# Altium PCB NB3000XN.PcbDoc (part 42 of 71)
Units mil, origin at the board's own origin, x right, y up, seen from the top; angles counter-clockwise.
Board outline 9527.56 x 6929.77 mil, 6 copper layers (Top Layer, GND+SHIELD, MidLayer1, MidLayer2, P2 - 3V3+5V0, Bottom Layer), stack 62.375 mil thick; 832 components, 1027 nets, 4655 pads, 4981 vias.
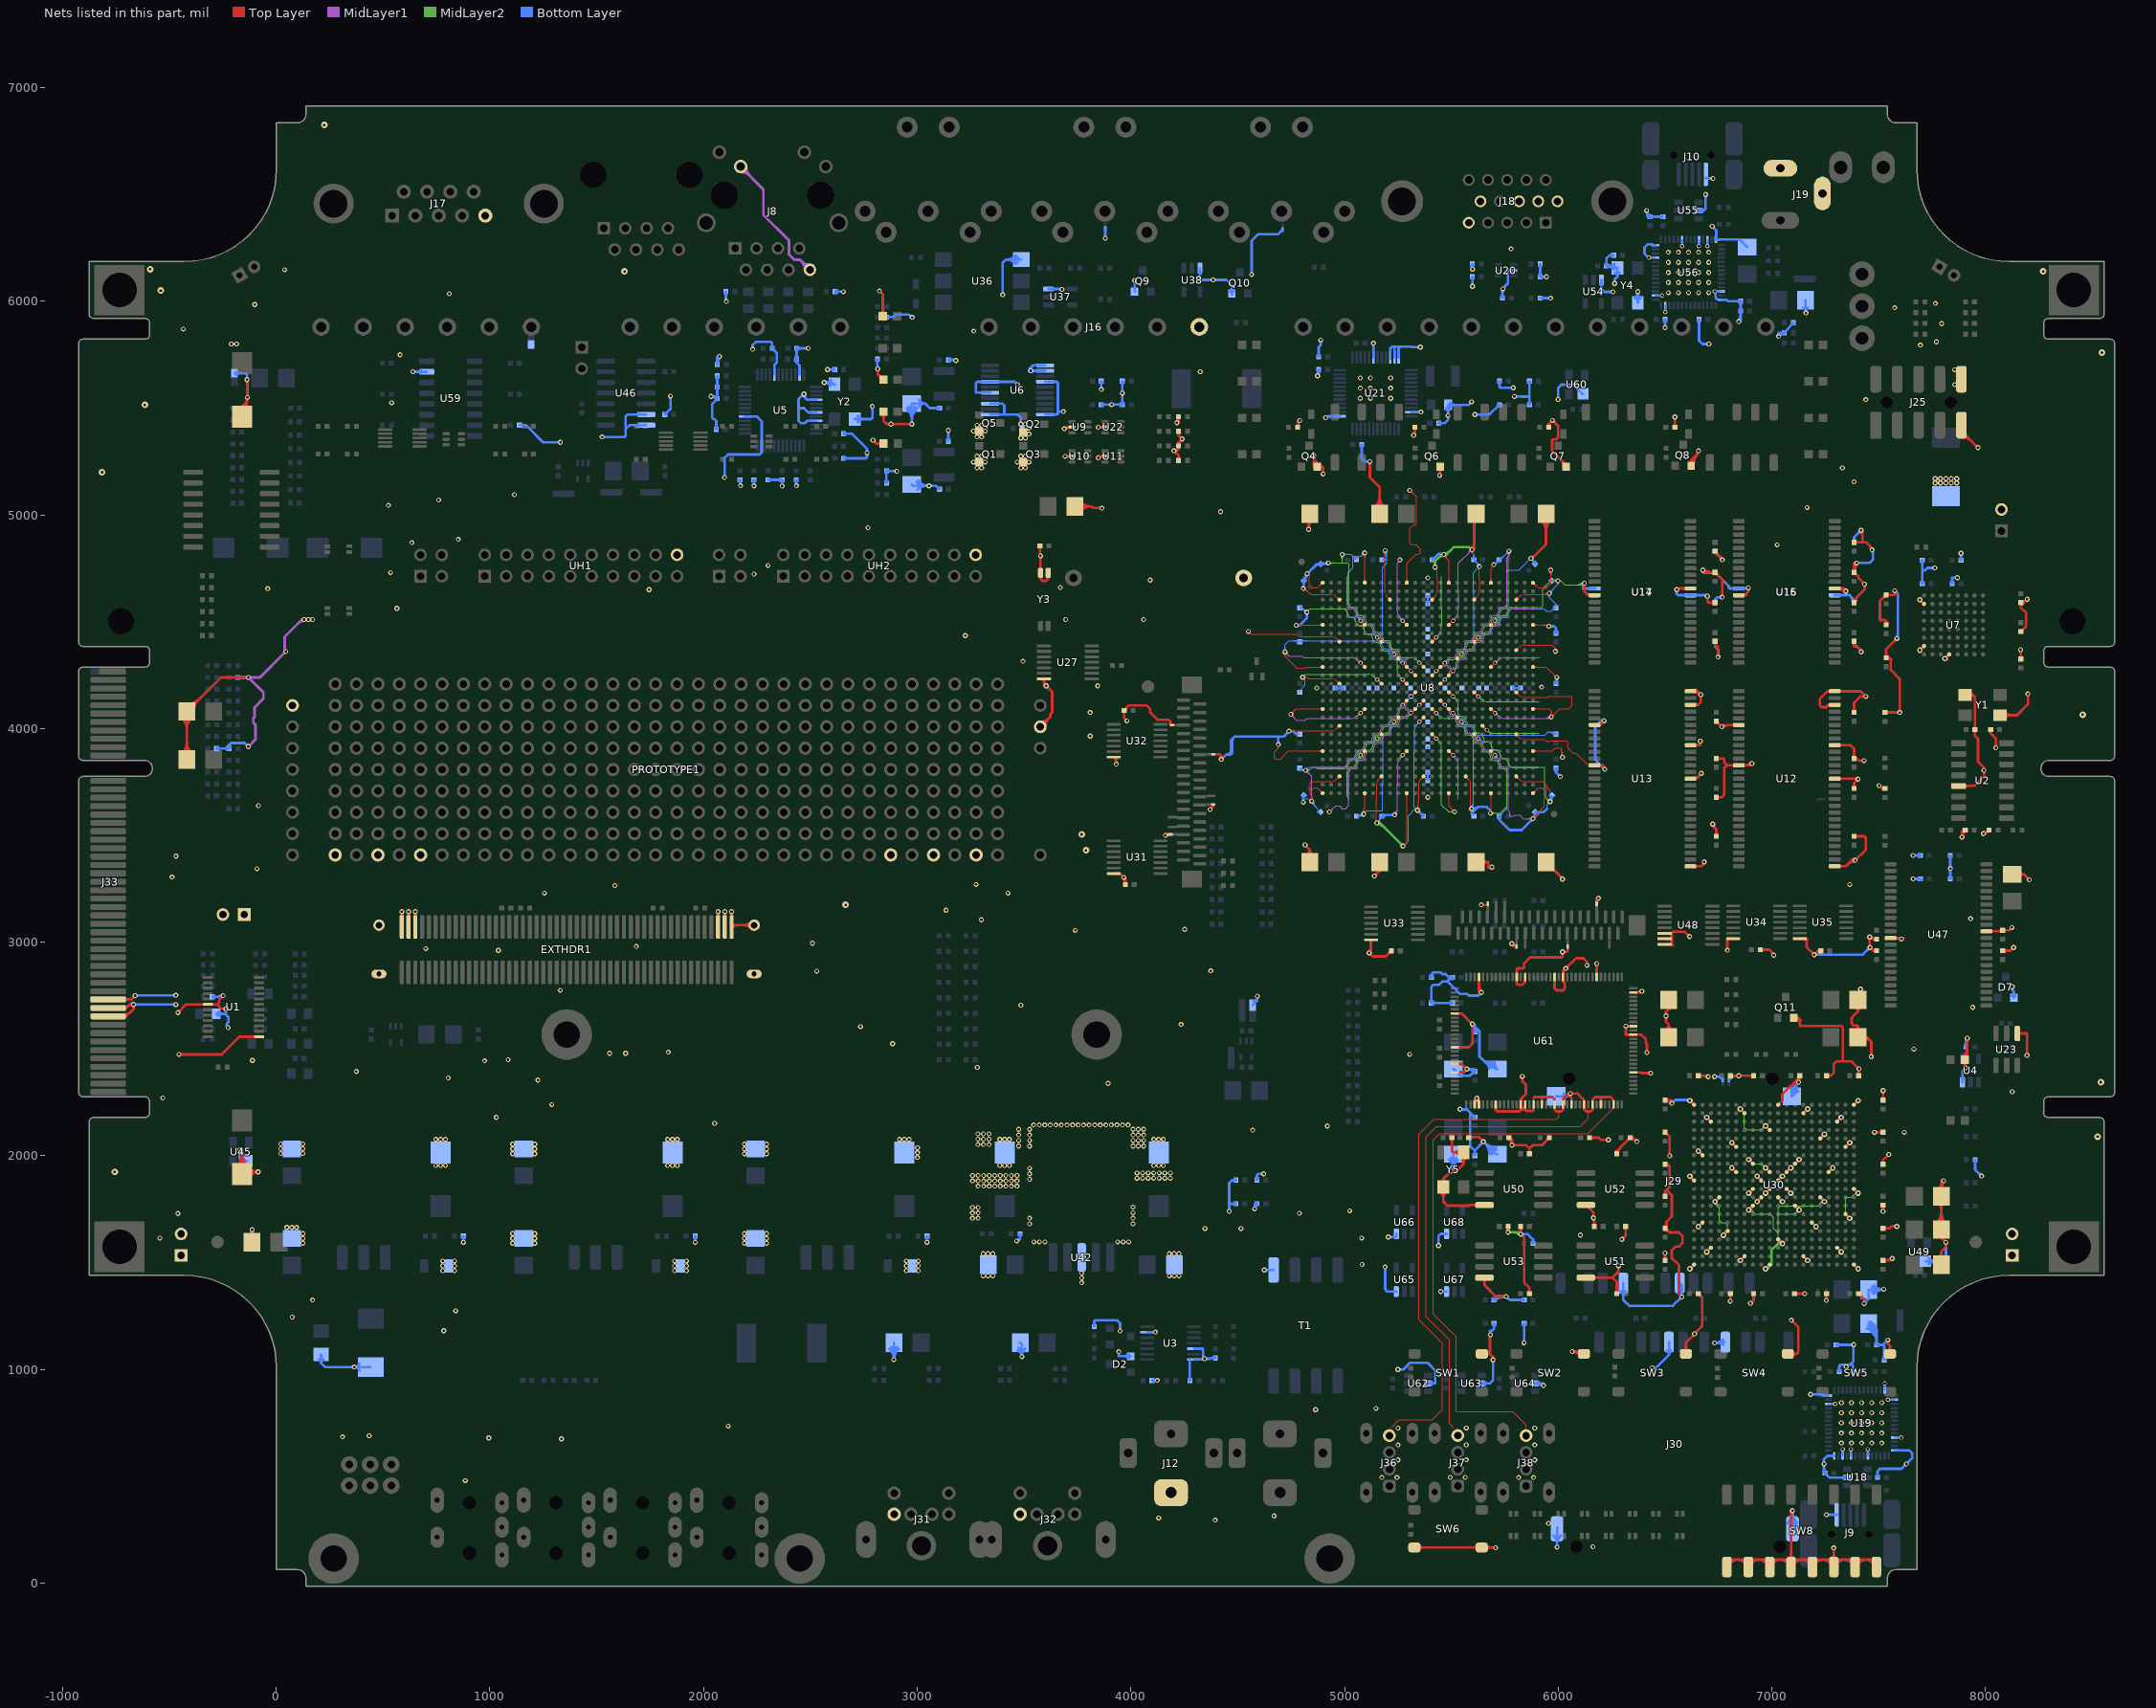
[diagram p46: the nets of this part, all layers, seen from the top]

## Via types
v1: diameter 23, hole 11.81, Top Layer to Bottom Layer, 3672 vias
v2: diameter 26, hole 11.81, Top Layer to Bottom Layer, 461 vias
v3: diameter 19, hole 11.81, Top Layer to Bottom Layer, tented both sides, 396 vias
v4: diameter 23.62, hole 11.81, Top Layer to Bottom Layer, 288 vias
v5: diameter 20, hole 11.81, Top Layer to Bottom Layer, 91 vias
v6: diameter 23, hole 11.81, Top Layer to Bottom Layer, tented both sides, 50 vias
v7: diameter 31, hole 11.81, Top Layer to Bottom Layer, 15 vias
v8: diameter 27.56, hole 11.81, Top Layer to Bottom Layer, tented both sides, 4 vias
v9: diameter 29, hole 11.81, Top Layer to Bottom Layer, 3 vias
v10: diameter 21, hole 11.81, Top Layer to Bottom Layer, 1 vias

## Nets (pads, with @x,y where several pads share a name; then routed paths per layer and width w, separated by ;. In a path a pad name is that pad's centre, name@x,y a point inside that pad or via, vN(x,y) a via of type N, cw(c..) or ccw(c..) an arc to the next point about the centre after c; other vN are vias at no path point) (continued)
GND: (continued)
  Top Layer w12: J33.A40@-785.98,2652.86 -701.48,2652.86 ; J33.A39@-785.98,2692.23 -701.48,2692.23 ; J33.A38@-785.98,2731.6 -678.25,2731.6 v1(-659.81,2750.04) ; J33.A39@-718.03,2688.12 ccw(c-713.87,2706.15) -700.79,2693.07 ; J33.A40@-717.08,2648.64 ccw(c-717.08,2676.13) -697.64,2656.69 ; J33.A40@-717.08,2660.64 ccw(c-717.08,2717.11) -677.16,2677.18 ; J33.A39@-715.33,2699.81 ccw(c-708.13,2731.03) -685.48,2708.37 ; J33.A38@-711.58,2726.1 cw(c-698.3,2712.82) -698.3,2731.6 cw(c-698.3,2750.38) J33.A38@-711.58,2737.1 ; J33.A40@-710.87,2648.18 cw(c-701.48,2641.09) -701.48,2652.86 ; J33.A40@-710.87,2657.54 ccw(c-701.48,2664.63) -701.48,2652.86 ; J33.A39@-710.87,2687.55 cw(c-701.48,2680.46) -701.48,2692.23 ; J33.A39@-710.87,2696.91 ccw(c-701.48,2704) -701.48,2692.23 ; -694.14,2699.71 cw(c-679.79,2685.36) v1@-670.63,2703.47 ; -686.64,2707.21 cw(c-668.14,2688.72) v1@-668.14,2714.87 ; -682.43,2711.42 cw(c-671.92,2700.91) v1@-665.21,2714.17 ; v1@-672.03,2712.26 cw(c-681.42,2721.65) -681.42,2708.37 cw(c-681.42,2695.1) -672.03,2704.49 cw(c-681.42,2695.1) -668.14,2695.1 cw(c-654.86,2695.1) v1@-664.25,2704.49 ; v1@-665.31,2750.04 cw(c-678.59,2750.04) -669.2,2740.65 cw(c-659.81,2731.26) v1@-659.81,2744.54 ; v4(-460,2670) -420.98,2709.02 U1.6@-320,2709.02 -276.78,2709.02 ; v4@-460,2675.81 ccw(c-460,2689.84) -450.08,2679.92 ccw(c-440.16,2670) v4@-454.19,2670 ; v4(-455,2475) -255,2475 -172.17,2557.83 U1.13@-79.84,2557.83 ; v4@-450.89,2470.89 cw(c-440.97,2460.97) -440.97,2475 cw(c-440.97,2489.03) v4@-450.89,2479.11 ; C191.2@-441.59,3882.53 ccw(c-498.56,3939.5) -417.99,3939.5 ; C3.2@-441.59,4052.47 cw(c-498.56,3995.5) -417.99,3995.5 cw(c-337.43,3995.5) C3.2@-394.4,4052.47 ; C191.2@-433.1,3874.05 ccw(c-469.58,3910.53) -417.99,3910.53 ccw(c-366.4,3910.53) C191.2@-402.88,3874.05 ; C3.2@-433.1,4060.95 cw(c-469.58,4024.47) -417.99,4024.47 cw(c-366.4,4024.47) C3.2@-402.88,4060.95 ; C191.2@-417.99,3855 -417.99,4041.71 -418.14,4041.71 -418.14,4080 -418.14,4083.07 -417.99,4083.22 C3.2@-417.99,4080 -258.62,4239.37 v1(-130.48,4239.37) ; -417.99,3939.5 ccw(c-337.43,3939.5) C191.2@-394.4,3882.53 ; C3.2@-417.99,4105.31 ccw(c-417.99,4166.4) -374.79,4123.2 ; C3.2@-417.99,4117.31 ccw(c-417.99,4207.37) -354.3,4143.69 ; C3.2@-396.62,4083.94 cw(c-354.53,4083.94) C3.2@-384.29,4113.7 ; C3.2@-384.62,4083.94 cw(c-313.56,4083.94) -363.81,4134.18 ; v1@-253.98,2750.04 cw(c-267.25,2750.04) -257.86,2740.65 cw(c-248.48,2731.26) v1@-248.48,2744.54 ; v1(-248.48,2750.04) -265.4,2733.12 -265.4,2720.4 -276.78,2709.02 ; v1@-238.36,2684.49 ccw(c-247.75,2675.1) -247.75,2688.37 ccw(c-247.75,2701.65) v1@-238.36,2692.26 ; v1(-234.48,2688.37) -256.14,2688.37 -276.78,2709.02 ; C2.2@-188.68,1947.4 ccw(c-256.93,2016.62) -159.72,2016.62 ; C2.2@-180.26,1938.86 ccw(c-228.64,1987.93) -159.72,1987.93 ccw(c-90.8,1987.93) C2.2@-139.19,1938.86 ; v1@-175.03,2024.15 cw(c-211.99,1987.2) -159.72,1987.2 ; C1.2@-171.72,5502.49 ccw(c-186.17,5550.04) v1@-136.48,5550.04 ; v1(-171.14,2028.04) -159.72,2016.62 ; C1.2@-168.23,5491.01 ccw(c-181.25,5533.85) -136.48,5533.85 ; v1@-166.55,2032.64 cw(c-183.02,2016.17) -159.72,2016.17 ; C1.2@-164.74,5479.53 ccw(c-176.33,5517.66) -136.48,5517.66 ; C1.2@-159.72,5459.09 -136.48,5459.09 v1@-136.48,5550.04 ; v1@-140.36,5629.49 cw(c-149.75,5620.1) -136.48,5620.1 cw(c-123.2,5620.1) v1@-132.59,5629.49 ; C2.2@-137.61,1937.17 ccw(c-111.07,1960.15) -111.07,1925.04 ; C1.2@-136.48,5506.48 ccw(c-116.28,5506.48) C1.2@-130.56,5492.2 ; -136.48,5532.74 cw(c-117.51,5532.74) v1@-130.92,5546.15 ; -136.48,5567.34 ccw(c-117.51,5567.34) v1@-130.92,5553.93 ; v1(-136.48,5633.37) v1@-136.48,5550.04 ; v1@-134.36,4235.49 ccw(c-143.75,4226.1) -143.75,4239.37 ccw(c-143.75,4252.65) v1@-134.36,4243.26 ; C2.2@-133.1,1905.94 cw(c-103.44,1892.47) -103.44,1925.04 ; C2.2@-130.77,1947.4 cw(c-62.52,2016.62) -159.72,2016.62 ; C2.2@-128.54,1945.02 ccw(c-84.81,1982.87) v1(-84.81,1925.04) ; C4.2@-128.45,1628.51 ccw(c-141.8,1654.04) v1@-112.99,1654.04 ; C2.2@-122.17,1900.98 cw(c-84.81,1884.01) v1(-84.81,1925.04) ; v1@-116.7,1650.15 cw(c-125.65,1641.2) -112.99,1641.2 ; C4.2@-112.99,1595 v1@-112.99,1654.04 ; -112.99,1640.32 cw(c-99.09,1640.32) v1@-108.92,1650.15 ; v1(-112.81,1654.04) v1@-112.99,1654.04 ; C4.2@-97.53,1628.51 cw(c-84.18,1654.04) v1@-112.99,1654.04 ; v1@-88.7,1921.15 ccw(c-98.09,1911.76) -98.09,1925.04 ccw(c-98.09,1938.32) v1@-88.7,1928.93 ; v1@-84.81,1924.76 v1(-84.81,1925.04) ; v1@583.97,3139.15 cw(c574.2,3129.38) 588.01,3129.38 ; v1(587.86,3143.04) 588.01,3142.88 EXTHDR1.99@588.01,3071.85 ; 588.01,3130.14 cw(c600.76,3130.14) v1@591.75,3139.15 ; v1@615.46,3139.15 cw(c605.7,3129.38) 619.51,3129.38 ; EXTHDR1.97@619.51,3071.85 v1@619.51,3142.88 ; 619.51,3130.14 cw(c632.25,3130.14) v1@623.24,3139.15 ; v1@646.96,3139.15 cw(c637.19,3129.38) 651.01,3129.38 ; EXTHDR1.95@651.01,3071.85 v1@651.01,3142.88 ; 651.01,3130.14 cw(c663.75,3130.14) v1@654.74,3139.15 ; v1@2064.28,3139.15 cw(c2054.52,3129.38) 2068.33,3129.38 ; EXTHDR1.5@2068.33,3071.85 v1@2068.33,3142.88 ; 2068.33,3130.14 cw(c2081.07,3130.14) v1@2072.06,3139.15 ; v1@2095.78,3139.15 cw(c2086.01,3129.38) 2099.83,3129.38 ; EXTHDR1.3@2099.83,3071.85 v1@2099.83,3142.88 ; 2099.83,3130.14 cw(c2112.57,3130.14) v1@2103.56,3139.15 ; v1@2127.28,3139.15 cw(c2117.51,3129.38) 2131.32,3129.38 ; EXTHDR1.1@2131.32,3071.85 v1@2131.32,3142.88 ; EXTHDR1.1@2131.32,3079.72 EXTHDR1.MH1@2236.94,3079.72 ; 2131.32,3130.14 cw(c2144.07,3130.14) v1@2135.06,3139.15 ; EXTHDR1.1@2134.15,3069.02 cw(c2159.99,3043.18) 2159.99,3079.72 ; EXTHDR1.MH1@2222.39,3065.17 ccw(c2187.27,3030.05) 2187.27,3079.72 ccw(c2187.27,3129.39) EXTHDR1.MH1@2222.39,3094.27 ; v1@2793.19,5344.54 cw(c2793.19,5331.26) 2802.58,5340.65 cw(c2811.97,5350.04) v1@2798.69,5350.04 ; v1(2793.19,5350.04) 2809.52,5333.71 ; v1@2811.3,5679.49 cw(c2801.91,5670.1) 2815.19,5670.1 cw(c2828.47,5670.1) v1@2819.08,5679.49 ; v1(2815.19,5683.37) 2815.19,5660.15 LED5.2@2842.08,5633.26 ; v1(2823.52,6048.37) 2839.27,6032.63 LED4.2@2839.27,5930 ; LED5.2@2828.4,5633.26 ccw(c2795.36,5633.26) 2818.72,5656.62 ccw(c2842.08,5679.99) LED5.2@2842.08,5646.95 ; LED4.2@2829.6,5939.68 ccw(c2806.23,5963.04) 2839.27,5963.04 ccw(c2872.31,5963.04) LED4.2@2848.95,5939.68 ; LED7.2@2832.37,5324.12 ccw(c2809.52,5301.69) 2809.52,5333.71 ; LED7.2@2832.37,5343.3 cw(c2809.52,5365.74) 2809.52,5333.71 ; LED6.2@2832.41,5473.79 cw(c2809.04,5450.43) 2842.08,5450.43 cw(c2875.12,5450.43) LED6.2@2851.76,5473.79 ; LED6.2@2842.08,5483.47 2842.08,5440.99 2858.07,5425 v1(2975,5425) ; LED7.2@2842.14,5333.71 2809.52,5333.71 ; v1@2971.11,5421.11 ccw(c2961.72,5411.72) 2961.72,5425 ccw(c2961.72,5438.28) v1@2971.11,5428.89 ; C116.2@3570.22,4850.89 cw(c3560.3,4840.97) 3574.33,4840.97 cw(c3588.36,4840.97) C116.2@3578.44,4850.89 ; Y3.3@3573.17,4713.1 cw(c3563.25,4703.17) 3577.28,4703.17 cw(c3591.31,4703.18) Y3.3@3581.39,4713.1 ; Y3.3@3573.17,4744.94 ccw(c3563.25,4754.86) 3577.28,4754.86 ccw(c3591.31,4754.85) Y3.3@3581.39,4744.94 ; v1@3573.4,4804.73 cw(c3564.01,4795.34) 3577.28,4795.34 cw(c3590.56,4795.34) v1@3581.17,4804.73 ; 3574.33,4829.02 ccw(c3597.69,4829.02) v1@3581.17,4812.5 ; C116.2@3574.33,4855 3574.33,4811.57 v1(3577.28,4808.61) Y3.3@3577.28,4729.02 3577.28,4700.04 3585.62,4691.71 3604.38,4691.71 3612.72,4700.04 Y3.2@3612.72,4729.02 ; TP8.1@3576.12,4008.23 3623.09,4055.2 3623.09,4065.94 3631.86,4074.71 3631.86,4172.04 v1(3603.86,4200.04) ; TP8.1@3576.12,4032.23 ccw(c3576.12,4090.18) 3617.09,4049.21 ccw(c3658.06,4008.23) TP8.1@3600.12,4008.23 ; 3592.8,4209.18 ccw(c3610.73,4209.18) v1@3599.95,4194.85 ; v1@3598.52,4200.04 v1(3603.86,4200.04) ; v1@3603.86,4194.54 cw(c3603.86,4181.26) 3613.25,4190.65 cw(c3622.64,4200.04) v1@3609.36,4200.04 ; v1@3607.16,4204.44 cw(c3628.82,4233.23) U27.7@3592.8,4233.23 3592.8,4211.1 v1(3603.86,4200.04) ; Y3.2@3608.61,4713.1 cw(c3598.69,4703.17) 3612.72,4703.17 cw(c3626.74,4703.18) Y3.2@3616.83,4713.1 ; v1@3689.9,5397.84 cw(c3716.14,5371.6) U9.2@3716.14,5408.72 ; v1@3692.31,5274.49 v1(3692.19,5274.37) U10.2@3725,5274.41 ; v1@3692.31,5400.26 3702.64,5410.59 U9.2@3725,5410.59 ; v1@3695.89,5403.84 cw(c3709.89,5389.84) U9.2@3715.6,5408.8 ; v1@3696.08,5270.49 cw(c3705.55,5261.01) 3705.55,5274.41 ; v1@3696.08,5278.26 ccw(c3705.39,5287.57) 3705.39,5274.41 ; C115.2@3737.99,5040 3814.23,5040 ; C115.2@3753.69,5025.5 cw(c3786.81,4994.92) 3786.81,5040 cw(c3786.81,5085.08) C115.2@3753.69,5054.5 ; C115.2@3762.51,5017.36 cw(c3814.23,4969.6) 3814.23,5040 ; C115.2@3762.51,5062.64 ccw(c3814.23,5110.4) 3814.23,5040 ; 3846.42,5033.37 cw(c3846.42,5013.27) v1@3860.64,5027.49 ; v1(3847.19,5267.04) v1@3847.19,5274.37 ; v1(3847.19,5410.71) 3847.31,5410.59 U22.2@3880,5410.59 ; v1@3847.22,5274.41 U11.2@3880,5274.41 ; v1@3851.08,5263.15 cw(c3878.26,5235.97) U11.2@3878.26,5274.41 ; v1@3851.08,5406.82 cw(c3860.18,5397.71) 3860.18,5410.59 ; v1@3851.08,5414.6 ccw(c3860.75,5424.27) 3860.75,5410.59 ; v1(3864.52,5031.37) 3856.19,5031.37 3854.19,5033.37 3820.86,5033.37 3814.23,5040 ; U31.7@3920,3321.46 3949.11,3321.46 v1(3966.86,3303.71) 3974.33,3296.23 C124.1@3974.33,3270 ; U32.7@3926.46,3865 3931.86,3859.6 v1(3931.86,3833.37) ; U32.7@3926.46,3866.46 U32.7@3920,3866.46 ; v1@3927.97,3837.26 ccw(c3918.58,3846.65) 3931.86,3846.65 ccw(c3945.14,3846.65) v1@3935.75,3837.26 ; U32.7@3928.54,3862.92 ccw(c3920,3854.39) U32.7@3920,3866.46 ; v1@3931.86,3837.83 ccw(c3891.37,3837.83) U32.7@3920,3866.46 ; 3931.86,3852.76 ccw(c3918.02,3852.76) U32.7@3920,3866.46 ; v1@3961.36,3303.71 ccw(c3948.08,3303.71) 3957.47,3313.1 ccw(c3966.86,3322.49) v1@3966.86,3309.21 ; v1@3962.97,3299.82 cw(c3935.54,3272.39) C124.1@3974.33,3272.39 ; 3969.19,4070.63 cw(c3983.7,4070.63) 3973.44,4080.89 ccw(c3983.36,4070.97) 3969.33,4070.97 ccw(c3955.3,4070.97) 3965.22,4080.89 cw(c3955.64,4071.31) 3969.19,4071.31 ; 3969.33,4056.71 C121.1@3969.33,4085 ; C124.1@3970.22,3274.11 ccw(c3960.3,3284.03) 3974.33,3284.03 ccw(c3988.36,3284.03) C124.1@3978.44,3274.11 ; C121.1@3975.14,4085 cw(c3995.24,4085) 3981.03,4099.21 ; v1(3981.86,4036.04) 3969.19,4048.71 3969.19,4085 3969.19,4087.37 3990.19,4108.37 4073.52,4108.37 4090.19,4091.71 4090.19,4075.04 4123.52,4041.71 4176.67,4041.71 4185,4033.37 NT28.2@4185,4020 ; v1(4161.86,3500.04) 4161.86,3508.33 4165.19,3505 NT31.2@4185,3505 ccw(c4185,3479.67) v1@4165.99,3496.41 ; 4185,4022.71 ccw(c4193.8,4022.71) NT28.2@4187.58,4016.49 ; v1@4201.86,5294.54 cw(c4201.86,5281.26) 4211.25,5290.65 cw(c4220.64,5300.04) v1@4207.36,5300.04 ; v1@4204.22,5305.01 ccw(c4211.64,5320.55) 4223.82,5308.37 ; v1@4212.18,5436.41 ccw(c4194.09,5460) R124.1@4223.82,5460 ; v1(4215.52,5432.04) 4216.86,5433.37 4222.78,5433.37 4223.82,5434.41 R124.1@4223.82,5460 ; R93.1@4217.17,5323.16 cw(c4234.81,5324.92) 4222.28,5337.46 ; R95.1@4220.06,5259.25 ccw(c4210.98,5268.33) 4223.82,5268.33 ccw(c4236.66,5268.33) R95.1@4227.58,5259.25 ; R93.1@4220.06,5319.08 cw(c4210.98,5310) 4223.82,5310 ; R93.1@4220.06,5327.59 ccw(c4210.98,5336.67) 4223.82,5336.67 ccw(c4236.66,5336.67) R93.1@4227.58,5327.59 ; R91.1@4220.06,5387.41 cw(c4210.98,5378.33) 4223.82,5378.33 cw(c4236.66,5378.33) R91.1@4227.58,5387.41 ; R124.1@4220.06,5455.75 cw(c4210.98,5446.67) 4223.82,5446.67 cw(c4236.66,5446.67) R124.1@4227.58,5455.75 ; R95.1@4223.82,5255 4223.82,5278.08 v1(4201.86,5300.04) 4215.49,5300.04 4223.82,5308.37 ; 4223.82,5310 cw(c4236.66,5310) R93.1@4227.58,5319.08 ; R91.1@4223.82,5391.67 4223.82,5371.71 4228.82,5366.71 ; 4228.86,5366.71 v1(4240.19,5355.37) ; R93.1@4229.11,5324.35 cw(c4267.39,5328.17) v1(4240.19,5355.37) ; 4230.74,5364.79 ccw(c4240.19,5374.24) v1@4240.19,5360.87 ; 4230.83,5364.7 cw(c4221.5,5355.37) 4234.69,5355.37 cw(c4221.41,5355.37) 4230.8,5345.99 cw(c4240.19,5336.6) v1@4240.19,5349.87 ; v1(4370.52,3621.37) 4385,3635.85 NT30.2@4385,3645 ; v1@4377.35,3628.2 ccw(c4366.65,3638.9) NT30.2@4380.5,3645 ; NT29.2@4385,3880 4414.86,3880 4418.86,3876 ; 4418.86,3876 ccw(c4438.69,3876) v1@4426.82,3860.11 ; 4425.76,3869.1 cw(c4414.72,3858.06) v1@4429.8,3854.03 ; R97.1@4777.42,5414.25 ccw(c4768.34,5423.33) 4781.18,5423.33 ccw(c4794.02,5423.33) R97.1@4784.94,5414.25 ; R97.1@4781.18,5408.75 cw(c4820.38,5408.75) v1@4793.9,5437.65 ; R97.1@4781.18,5410 4781.18,5432.71 v1(4790.19,5441.71) ; v1@4815.19,3450.21 cw(c4815.19,3436.93) 4824.58,3446.32 cw(c4833.97,3455.71) v1@4820.69,3455.71 ; v1(4815.19,3455.71) 4837.01,3433.89 ; C278.2@4821.62,3408.55 ccw(c4808.45,3433.89) 4837.01,3433.89 ; v1@4827.97,4936.26 ccw(c4818.58,4945.65) 4831.86,4945.65 ccw(c4845.14,4945.65) v1@4835.75,4936.26 ; C276.2@4830.3,4968.37 cw(c4828.61,4960.15) 4837.01,4960.15 ; v1(4831.86,4932.37) 4831.86,4955 4837.01,4960.15 ; C278.2@4837.01,3375 4837.01,3433.89 ; C276.2@4837.01,5005 4837.01,4960.15 ; C276.2@4843.71,4968.37 ccw(c4845.4,4960.15) 4837.01,4960.15 ; C278.2@4852.4,3408.55 cw(c4865.57,3433.89) 4837.01,3433.89 ; v1@4852.97,5273.82 cw(c4843.58,5264.43) 4856.86,5264.43 cw(c4870.14,5264.43) v1@4860.75,5273.82 ; Q4.3@4856.86,5225.79 v1(4856.86,5277.71) ccw(c4906.35,5277.71) Q4.3@4878.9,5236.52 ; 4856.86,5255.29 ccw(c4891.41,5255.29) Q4.3@4872.24,5226.54 ; Q4.3@4872.22,5225.02 cw(c4883.53,5211.12) 4896.21,5223.79 ; Q4.3@4872.28,5225.06 cw(c4882.73,5203.89) 4899.42,5220.58 ; Q4.3@4872.4,5225.79 4894.21,5225.79 ; Q4.3@4882.17,5219.32 cw(c4894.21,5211.35) 4894.21,5225.79 ; Q4.3@4882.17,5232.26 ccw(c4894.21,5240.23) 4894.21,5225.79 ; v1@4895.97,5195.6 ccw(c4886.58,5204.99) 4899.86,5204.99 ccw(c4913.14,5204.99) v1@4903.75,5195.6 ; v1(4899.86,5191.71) 4899.86,5220.14 4894.21,5225.79 ; v1@5111.3,2953.93 ccw(c5081.79,2983.44) 5123.52,2983.44 ; v1@5114.97,5246.15 cw(c5105.58,5236.76) 5118.86,5236.76 cw(c5132.14,5236.76) v1@5122.75,5246.15 ; v1@5115.19,2944.54 cw(c5115.19,2931.26) 5124.58,2940.65 cw(c5133.97,2950.04) v1@5120.69,2950.04 ; v1(5118.86,5250.04) 5118.86,5176.14 5164.33,5130.67 5164.33,5107.04 C260.2@5164.33,5005 ; U33.7@5123.52,3011.46 5123.52,2958.37 v1(5115.19,2950.04) 5131.86,2933.37 5192.71,2933.37 C122.1@5219.33,2960 ; v1(5140,3310) 5164.33,3334.33 C265.2@5164.33,3375 ; v1@5140,3315.5 ccw(c5140,3328.78) 5149.39,3319.39 ccw(c5158.78,3310) v1@5145.5,3310 ; C260.2@5140.73,5032.53 ccw(c5083.77,5089.5) 5164.33,5089.5 ; C260.2@5149.22,5024.05 ccw(c5112.74,5060.53) 5164.33,5060.53 ccw(c5215.92,5060.53) C260.2@5179.44,5024.05 ; 5164.33,5089.5 ccw(c5244.89,5089.5) C260.2@5187.93,5032.53 ; C122.1@5213.52,2960 cw(c5199.49,2960) 5209.41,2950.08 cw(c5219.33,2940.16) C122.1@5219.33,2954.19 ; v1@5319.64,5376.26 ccw(c5297.46,5398.44) R126.1@5328.82,5398.44 ; v1(5323.52,5372.37) 5323.52,5370.37 5323.82,5370.37 5324.67,5371.23 5328.82,5375.37 R126.1@5328.82,5410 ; R126.1@5325.06,5405.75 cw(c5315.98,5396.67) 5328.82,5396.67 cw(c5341.66,5396.67) R126.1@5332.58,5405.75 ; SW6.3@5327.13,166.81 5392.63,166.81 5392.52,166.71 5598.52,166.71 5598.52,166.81 ; SW6.3@5344.79,155.14 cw(c5372.96,126.98) 5372.96,166.81 cw(c5372.96,206.65) SW6.3@5344.79,178.48 ; Q6.3@5439.45,5216.19 cw(c5422.7,5198.04) 5447.4,5198.04 ; v1@5441.11,5188.89 ccw(c5425.92,5204.08) 5447.4,5204.08 ; v1(5445,5185) 5441.82,5185 5440.19,5183.37 5440.19,5191.04 5440.4,5191.04 5447.4,5198.04 ; Y5.2@5447.3,1834.3 cw(c5410.59,1797.59) 5462.5,1797.59 cw(c5514.41,1797.59) Y5.2@5477.7,1834.3 ; Q6.3@5447.4,5225.79 5447.4,5198.04 ; Y5.2@5453.02,1876.8 ccw(c5445.55,1892.02) 5462.5,1892.02 ; Q6.3@5455.35,5216.19 ccw(c5472.11,5198.04) 5447.4,5198.04 ; Y5.2@5471.98,1876.8 cw(c5479.46,1892.02) 5462.5,1892.02 ; v1@5493.02,1928.04 cw(c5479.75,1928.04) 5489.14,1918.65 cw(c5498.52,1909.26) v1@5498.52,1922.54 ; C157.1@5498.56,2080.89 cw(c5488.64,2070.97) 5502.67,2070.97 cw(c5516.7,2070.97) C157.1@5506.78,2080.89 ; v1@5502.41,1924.15 cw(c5511.8,1914.76) 5511.8,1928.04 cw(c5511.8,1941.32) v1@5502.41,1931.93 ; C157.1@5502.67,2085 5502.67,2022.33 5508.5,2016.5 ; U61.123@5516.83,2390.4 5556.55,2390.4 v1(5572.52,2406.37) 5549.13,2429.77 U61.121@5516.83,2429.77 ; U61.117@5516.83,2508.51 5548.52,2508.51 5548.52,2508.37 5581.86,2508.37 5598.52,2525.04 v1(5598.52,2616.71) 5549.24,2665.99 U61.109@5516.83,2665.99 ; Y5.4@5541.68,2001.94 ccw(c5508.5,1971.42) 5508.5,2016.5 ; Y5.4@5541.68,2031.06 cw(c5508.5,2061.58) 5508.5,2016.5 ; Y5.4@5542.6,1997 cw(c5508.99,1962.02) 5557.5,1962.02 ; Y5.4@5572.4,1997 ccw(c5606.01,1962.02) 5557.5,1962.02 ; v1@5572.52,2400.87 ccw(c5572.52,2387.6) 5563.14,2396.99 ccw(c5553.75,2406.37) 5567.02,2406.37 ccw(c5553.75,2406.37) 5563.14,2415.76 ccw(c5572.52,2425.15) v1@5572.52,2411.87 ; C169.1@5580.67,2085 5583.54,2087.87 5629.36,2087.87 v1(5650.52,2066.71) ; C169.1@5584.78,2080.89 cw(c5601.64,2064.03) 5601.64,2087.87 ; v1@5592.3,4840.93 ccw(c5557.16,4876.07) 5606.86,4876.07 ; v1@5593.02,2616.71 ccw(c5579.75,2616.71) 5589.14,2626.1 ccw(c5598.52,2635.49) v1@5598.52,2622.21 ; v1@5594.64,2612.82 cw(c5585.25,2603.43) 5598.52,2603.43 cw(c5611.8,2603.43) v1@5602.41,2612.82 ; v1(5596.19,4837.04) 5606.86,4847.71 C267.2@5606.86,5000.04 ; v1@5600.79,4832.44 ccw(c5586.13,4847.1) 5606.86,4847.1 ; U61.3@5609.37,2238.17 cw(c5642.58,2238.17) v4@5623.36,2265.26 ; U61.3@5609.37,2240 5609.37,2260.37 v4@5620,2260.37 ; 5609.37,2261.4 cw(c5626.1,2261.4) v4@5616.42,2275.05 ; 5611.72,2260.37 cw(c5611.72,2235.85) U61.4@5629.06,2253.19 ; C266.2@5615.67,3375 5671.48,3375 ; v4@5616.32,2265.5 cw(c5594.41,2238.66) U61.4@5629.06,2238.66 ; U50.4@5619.97,1764.5 ccw(c5606.69,1751.22) 5606.69,1770 ccw(c5606.69,1788.78) U50.4@5619.97,1775.5 ; v4(5620,2270) v4@5620,2260.37 ; SW6.4@5624.41,155.56 ccw(c5598.53,131.41) 5598.53,166.81 ; SW6.4@5624.41,178.07 cw(c5598.53,202.21) 5598.53,166.81 ; v4@5626.71,2260.37 ccw(c5626.71,2235.85) U61.3@5609.37,2253.19 ; U61.4@5629.06,2240 5629.06,2260.37 v4@5620,2260.37 ; 5629.06,2775.57 ccw(c5651.38,2775.57) v1@5635.59,2759.78 ; 5629.06,2804.54 ccw(c5680.35,2804.54) v1@5644.08,2768.26 ; U61.99@5629.06,2837.34 5629.06,2775.51 v1(5640.19,2764.37) ; SW1.3@5642.87,1073.58 5680.86,1073.58 ; v1@5645.02,2066.71 ccw(c5631.75,2066.71) 5641.14,2076.1 ccw(c5650.52,2085.49) v1@5650.52,2072.21 ; C266.2@5645.06,3359.21 cw(c5671.48,3345.01) 5671.48,3375 ; C266.2@5645.07,3390.79 ccw(c5671.48,3404.99) 5671.48,3375 ; U53.4@5649.5,1424.5 cw(c5636.22,1411.22) 5655,1411.22 cw(c5673.78,1411.22) U53.4@5660.5,1424.5 ; U53.4@5655,1430 5655,1395 5708.29,1341.71 v1(5756.86,1341.71) ; U50.4@5655,1770 5585.86,1770 5582.86,1767 5582.86,1766.71 5481.83,1766.71 5462.5,1786.04 Y5.2@5462.5,1853.5 Y5.2@5462.5,1855.99 ; SW6.4@5660.15,155.14 cw(c5688.31,126.98) 5688.31,166.81 cw(c5688.32,206.65) SW6.4@5660.15,178.48 ; SW1.3@5662.32,1064.02 cw(c5680.86,1050.84) 5680.86,1073.58 ; SW1.3@5662.32,1083.15 ccw(c5680.86,1096.33) 5680.86,1073.58 ; 5671.86,3375.04 5673.52,3373.37 5673.52,3351.71 ; 5673.52,3350.71 5677.52,3346.71 5690,3346.71 5695,3346.71 v4(5690,3351.71) ; 5680.86,1143.66 cw(c5701.57,1143.66) v1@5686.92,1158.3 ; v1(5683.03,1162.19) 5683.03,1165.53 5680.86,1167.71 5680.86,1073.58 ; 5690.92,166.81 cw(c5690.92,149.77) v1@5702.97,161.82 ; v1(5695,1045) 5695,1059.44 5680.86,1073.58 ; 5695.89,1058.55 cw(c5682.33,1045) v1@5701.5,1045 ; v1(5706.86,165.71) 5707.96,166.81 5706.86,166.81 SW6.4@5642.48,166.81 5598.52,166.81 ; U61.8@5707.8,2226.81 ccw(c5717.39,2221.61) 5709.67,2213.89 ; U61.8@5707.79,2240 5707.8,2217.37 5707.13,2216.71 5706.86,2216.71 5715.19,2208.37 5819.95,2208.37 5823.52,2211.95 ; v1@5752.97,1337.82 ccw(c5743.58,1328.43) 5743.58,1341.71 ccw(c5743.58,1354.99) v1@5752.97,1345.6 ; v1@5761.45,1646.26 ccw(c5751.25,1656.46) 5765.67,1656.46 ; C158.2@5761.56,1665.89 cw(c5751.64,1655.97) 5765.67,1655.97 cw(c5779.7,1655.97) C158.2@5769.78,1665.89 ; v1(5765.34,1642.37) 5765.67,1642.71 C158.2@5765.67,1670 ; 5765.67,1654.85 ccw(c5777.81,1654.85) v1@5769.22,1646.26 ; C187.2@5766.19,2080.16 cw(c5744.22,2047.18) v1@5783.86,2047.18 ; C187.2@5769.37,2079.19 cw(c5769.24,2064.57) 5783.86,2064.57 ; C187.2@5769.41,2079.19 cw(c5769.41,2065.16) 5779.33,2075.08 cw(c5789.26,2085) C187.2@5775.23,2085 ; C187.2@5769.41,2085 5783.86,2070.56 v1(5783.86,2050.04) 5850.17,2050.04 5865.67,2034.54 ; C187.2@5772.84,2090.15 cw(c5759.15,2069.59) 5783.86,2069.59 ; v1@5779.97,2053.93 ccw(c5770.58,2063.32) 5783.86,2063.32 ccw(c5797.14,2063.32) 5787.75,2053.93 ccw(c5797.14,2063.32) 5797.14,2050.04 ccw(c5797.14,2036.76) v1@5787.75,2046.15 ; v1@5782.86,2993 5795.86,2980 NT41.2@5805,2980 ; v1@5789.68,2986.18 ccw(c5798.38,2994.88) NT41.2@5805,2984.5 ; C164.2@5820.22,1665.89 cw(c5810.3,1655.97) 5824.33,1655.97 cw(c5838.36,1655.97) C164.2@5828.44,1665.89 ; U61.14@5823.52,2221.06 cw(c5831.65,2221.06) 5825.91,2226.81 ccw(c5843.59,2236.49) 5843.59,2216.33 ; U61.14@5823.52,2258.94 ccw(c5831.65,2258.94) 5825.91,2253.19 cw(c5857.84,2253.19) 5835.26,2275.78 ; 5824.33,1648.73 ccw(c5840.54,1648.73) v1@5829.08,1637.26 ; C164.2@5824.33,1670 5824.33,1642.57 5825.19,1641.71 v1(5825.19,1633.37) 5840.19,1618.37 5840.19,1406.71 5863.52,1383.37 5863.67,1383.37 5864.6,1382.45 ; U61.14@5825.9,2240 5825.91,2214.33 ; v1@5827.97,2368.49 cw(c5818.58,2359.1) 5831.86,2359.1 cw(c5845.14,2359.1) v1@5835.75,2368.49 ; v1(5831.86,2372.37) 5831.86,2350.04 5848.52,2333.37 5848.52,2289.04 5823.52,2264.04 5823.52,2211.95 ; 5839.44,2809.29 ccw(c5824.58,2824.14) U61.88@5845.59,2824.14 ; v1@5840.19,1116.71 v1(5840.19,1125.04) ; U61.15@5845.59,2226.81 cw(c5827.91,2236.49) 5827.91,2216.33 ; U61.15@5845.59,2240 5845.59,2214.33 ; U61.88@5845.59,2837.34 5845.59,2815.44 5830.19,2800.04 5809.86,2800.04 5806.22,2803.68 U61.90@5806.22,2837.34 5806.22,2873.37 5810.22,2877.37 5836.52,2877.37 5840.19,2881.04 5840.19,2900.37 5869.19,2929.37 6016.19,2929.37 6020,2933.18 v4(6020,2955) ; 5861.52,2038.71 5869.84,2038.71 ; C165.1@5861.56,1359.11 ccw(c5851.64,1369.03) 5865.67,1369.03 ccw(c5879.7,1369.03) 5869.78,1359.11 cw(c5884.88,1374.21) 5863.52,1374.21 ; C159.1@5861.56,2014.11 ccw(c5851.64,2024.03) 5865.67,2024.03 ccw(c5879.7,2024.03) C159.1@5869.78,2014.11 ; C165.1@5863.52,1352.85 5863.52,1355 5863.52,1381.37 5864.6,1382.45 ; C165.1@5865.67,1355 5865.67,1381.37 ; C159.1@5865.67,2010 5865.67,2034.54 ; v1(5872.19,4797.04) 5877.45,4797.04 5942.99,4862.59 C277.2@5942.99,5005 ; v1@5872.19,4802.54 ccw(c5872.19,4828.51) 5890.55,4810.15 ; C277.2@5919.4,4977.47 cw(c5862.43,4920.5) 5942.99,4920.5 cw(c6023.55,4920.5) C277.2@5966.59,4977.47 ; U61.19@5924.33,2240 5924.33,2275.04 ; C277.2@5927.88,4985.95 cw(c5891.4,4949.47) 5942.99,4949.47 cw(c5994.58,4949.47) C277.2@5958.1,4985.95 ; C279.2@5943.52,3340.37 C279.2@5943.52,3374.47 ; R257.2@5948.77,2075.08 cw(c5958.69,2065.16) R257.2@5958.69,2079.19 ; R257.2@5949.96,2076.27 ccw(c5941.72,2084.51) R257.2@5953.37,2084.51 ; R128.1@5950.15,5407.61 cw(c5961.06,5412.82) R128.1@5952.51,5421.37 ; R128.1@5952.42,5414.25 ccw(c5943.34,5423.33) 5956.18,5423.33 ccw(c5969.02,5423.33) R128.1@5959.94,5414.25 ; R128.1@5956.18,5410 5956.18,5425.04 5964.51,5433.37 ; R257.2@5958.69,2085 5923.69,2050 5881.13,2050 5869.84,2038.71 ; R128.1@5960.98,5412.78 cw(c5977.31,5420.58) 5964.51,5433.37 ; 5964.12,5432.98 cw(c5973.53,5423.57) 5973.52,5436.87 cw(c5973.52,5423.6) 5982.91,5432.99 cw(c5992.3,5442.37) v1@5979.02,5442.37 ; 5964.14,5433 ccw(c5954.77,5442.37) v1@5968.02,5442.37 ; U61.22@5983.39,2226.81 ccw(c5996.07,2222.82) 5986.67,2213.42 ; U61.22@5983.38,2240 5983.39,2216.71 ; U61.81@5983.38,2837.34 5983.39,2784.85 5993.19,2775.04 6023.52,2775.04 6031.86,2783.37 6031.86,2808.37 6026.86,2813.37 ; 6007.96,3310.03 cw(c5992.94,3295) v4@6014.19,3295 ; 6012.17,5259.39 cw(c5979.55,5226.77) Q7.3@6025.69,5226.77 ; v4@6015.89,2950.89 cw(c6005.97,2940.97) 6020,2940.97 cw(c6034.03,2940.97) 6024.11,2950.89 cw(c6034.03,2940.97) 6034.03,2955 cw(c6034.03,2969.03) v4@6024.11,2959.11 ; v4@6016.19,2951.19 v4(6020,2955) ; 6019.47,2213.42 ccw(c6010.07,2222.82) U61.24@6022.75,2226.81 ; v4(6020,3295) 6020,3297.99 C279.2@5943.52,3374.47 ; U61.24@6022.76,2240 6022.76,2216.71 ; U61.79@6022.75,2824.14 ccw(c6038.85,2824.14) 6027.47,2812.76 ; U61.79@6022.76,2837.34 6022.76,2817.37 6026.76,2813.37 6026.86,2813.37 ; 6034.21,2276.83 cw(c6056.86,2254.17) v1@6056.86,2286.21 ; v1@6035.52,2882.54 ccw(c6035.52,2895.82) 6044.91,2886.43 ccw(c6054.3,2877.04) v1@6041.02,2877.04 ; Q7.3@6037.4,5225.79 6037.4,5226.77 6040.19,5226.77 6040.19,5231.37 5971.52,5300.04 5971.52,5351.04 5973.52,5353.04 5990.19,5353.04 5999.86,5362.71 5999.86,5416.04 v1(5973.52,5442.37) 5964.52,5433.37 ; NT38.2@6045,2980 6045,2958.18 6041.82,2955 v4(6020,2955) ; v1@6060.75,2287.82 cw(c6070.14,2278.43) 6070.14,2291.71 cw(c6070.14,2304.99) v1@6060.75,2295.6 ; U61.26@6062.12,2240 6062.13,2271.71 6057.13,2276.71 6056.86,2276.71 v1(6056.86,2291.71) ; v1@6069.08,1079.82 cw(c6078.47,1070.43) 6078.47,1083.71 cw(c6078.47,1096.99) v1@6069.08,1087.6 ; 6087.36,1083.71 cw(c6087.36,1055.94) SW2.3@6110.61,1071.12 ; SW2.3@6100.56,1064.56 ccw(c6065.19,1041.47) v1(6065.19,1083.71) 6110.25,1083.71 SW2.3@6120.37,1073.58 ; 6115.86,2266.04 cw(c6103.01,2253.19) U61.29@6121.18,2253.19 ; v1@6118.64,4676.82 cw(c6109.25,4667.43) 6122.52,4667.43 cw(c6135.8,4667.43) v1@6126.41,4676.82 ; v1(6122.52,4680.71) 6122.52,4641.92 6140.19,4624.25 U17.12@6170.59,4624.25 ; U61.29@6123.52,2221.15 ccw(c6115.52,2221.15) 6121.18,2226.81 ccw(c6139.9,2226.81) 6126.66,2213.57 ; U61.29@6123.52,2240 6123.52,2216.71 6131.86,2208.37 6140,2208.37 6152.22,2208.37 6160.55,2216.71 ; U61.29@6123.52,2241.71 6123.52,2258.37 6090.19,2291.71 v1(6056.86,2291.71) ; 6128.95,4635.5 ccw(c6147.61,4654.16) U17.12@6152.32,4628.19 ; U51.4@6130,1430 6255,1430 ; U52.4@6130,1770 6165,1735 v1(6165,1710) 6169.33,1705.67 C160.2@6169.33,1670 ; v1@6130.97,2895.6 ccw(c6121.58,2904.99) 6134.86,2904.99 ccw(c6148.14,2904.99) v1@6138.75,2895.6 ; v1(6134.86,2891.71) 6134.86,2908.04 6117.86,2925.04 6083.52,2925.04 v1(6035.52,2877.04) 6023.52,2865.04 6023.52,2837.34 6023.52,2816.71 6026.86,2813.37 ; R258.2@6148.52,2085 R258.2@6147.44,2085 6190,2085 6200,2075 v1(6235,2075) ; R258.2@6151.2,2081.24 cw(c6160.28,2072.16) 6160.28,2085 cw(c6160.28,2097.84) R258.2@6151.2,2088.76 ; 6157.27,2213.42 ccw(c6147.87,2222.82) U61.31@6160.55,2226.81 ; U61.31@6160.55,2240 6160.55,2216.71 ; U61.31@6160.55,2253.19 cw(c6180.37,2253.19) 6166.35,2267.2 ; v1@6161.11,1706.11 cw(c6141.27,1686.27) 6169.33,1686.27 ; v1@6161.11,1713.89 ccw(c6151.72,1723.28) 6165,1723.28 ccw(c6178.28,1723.28) v1@6168.89,1713.89 ; U51.4@6165.03,1424.5 cw(c6178.31,1411.22) 6178.31,1430 cw(c6178.31,1448.78) U51.4@6165.03,1435.5 ; C160.2@6165.22,1674.11 ccw(c6155.3,1684.03) 6169.33,1684.03 ccw(c6183.36,1684.03) C160.2@6173.44,1674.11 ; U13.12@6170.59,3827.99 6208.19,3827.99 v1@6218.52,3817.66 ; U13.6@6170.59,4016.97 6196.12,4016.97 v1(6215.19,4036.04) ; v1@6176.64,2896.15 cw(c6167.94,2887.46) 6180.24,2887.46 ; NT39.2@6180,3178.66 cw(c6208.9,3178.66) v1@6191.78,3201.94 ; NT39.2@6180,3180 6180,3206.37 6180,3206.56 6180.19,3206.37 v1(6188.52,3206.37) ; U61.71@6180.24,2837.34 6180.24,2891.71 6180.52,2891.71 v1(6180.52,2900.04) ; 6180.24,2886.06 cw(c6194.5,2886.06) v1@6184.41,2896.15 ; U13.6@6188.15,4020.97 ccw(c6188.15,4049.86) v1@6208.58,4029.43 ; U61.33@6199.92,2240 6199.92,2266.71 6191.59,2275.04 ; v1@6209.69,4036.04 cw(c6196.41,4036.04) 6205.8,4026.65 cw(c6215.19,4017.26) v1@6215.19,4030.54 ; v1@6231.11,2071.11 ccw(c6221.72,2061.72) 6221.72,2075 ccw(c6221.72,2088.28) v1@6231.11,2078.89 ; 6253.27,2266.96 cw(c6239.51,2253.19) U61.36@6258.97,2253.19 ; U61.36@6258.97,2240 6258.98,2261.26 6245.19,2275.04 6191.59,2275.04 ; C162.2@6268.14,2010 cw(c6284.95,2010) 6273.06,2021.88 ; C161.1@6270.22,1359.11 ccw(c6260.3,1369.03) 6274.33,1369.03 ccw(c6288.36,1369.03) C161.1@6278.44,1359.11 ; C162.2@6270.42,2014.3 ccw(c6262.36,2023.15) 6274.33,2023.15 ccw(c6286.3,2023.15) C162.2@6278.24,2014.3 ; C161.1@6274.33,1355 6274.33,1410.67 6255,1430 ; C162.2@6274.33,2010 6274.33,2023.15 R259.2@6336.18,2085 6350.23,2085 v1(6368.52,2066.71) ; v1@6278.11,1482.11 cw(c6268.72,1472.72) 6282,1472.72 cw(c6295.28,1472.72) v1@6285.89,1482.11 ; C162.2@6280.14,2010 cw(c6325.92,2010) 6293.55,2042.37 ; v1(6282,1486) 6282,1457 6255,1430 ; v1(6298.52,1609.37) 6315.67,1626.52 C163.1@6315.67,1670 ; v1@6298.52,1614.87 ccw(c6298.52,1628.15) 6307.91,1618.76 ccw(c6317.3,1609.37) v1@6304.02,1609.37 ; C163.1@6311.56,1665.89 cw(c6301.64,1655.97) 6315.67,1655.97 cw(c6329.7,1655.97) C163.1@6319.78,1665.89 ; v1@6312.64,2603.15 cw(c6303.25,2593.76) 6316.52,2593.76 cw(c6329.8,2593.76) 6320.41,2603.15 cw(c6329.55,2594.02) 6329.55,2606.94 ; v1@6320.41,2610.93 ccw(c6330.06,2620.57) 6330.06,2606.94 ; R259.2@6326.26,2075.08 cw(c6336.18,2065.16) 6336.18,2079.19 cw(c6336.18,2031.24) v1@6370.09,2065.14 ; R259.2@6327.45,2076.27 ccw(c6319.21,2084.51) R259.2@6330.86,2084.51 ; R259.2@6336.18,2091.19 cw(c6336.18,2072.21) 6349.6,2085.63 ; R259.2@6338.94,2079.96 cw(c6346.8,2067.03) 6357.5,2077.73 ; R259.2@6339.94,2081.24 cw(c6349.02,2072.16) 6349.02,2085 cw(c6349.02,2097.84) R259.2@6339.94,2088.76 ; U61.53@6351.52,2566.71 6316.52,2566.71 6316.52,2567.57 ; U61.44@6351.93,2390.4 6388.55,2390.4 6391.58,2387.37 v1(6433.19,2387.37) ; U61.55@6351.93,2606.94 v1@6316.52,2606.94 ; U61.63@6351.93,2764.42 6375,2764.42 ; v1@6363.02,2066.71 ccw(c6349.75,2066.71) 6359.14,2076.1 ccw(c6368.52,2085.49) v1@6368.52,2072.21 ; U61.63@6364.67,2764.42 ccw(c6364.67,2796.9) v1@6387.64,2773.93 ; U61.63@6365.13,2764.42 ccw(c6366.86,2783.81) v1@6380.62,2770.04 ; v1@6386.43,2772.11 cw(c6375,2776.75) 6375,2764.42 ; v1@6394.86,2766.71 v1(6391.52,2770.04) v1@6380.62,2770.04 ; v1@6411.3,2487.26 ccw(c6401.91,2496.65) 6415.19,2496.65 ccw(c6428.47,2496.65) v1@6419.08,2487.26 ; v1(6415.19,2483.37) 6415.19,2525 6410.19,2530 6410.19,2545.71 6389.19,2566.71 6389.19,2566.9 6388.52,2567.57 U61.53@6351.93,2567.57 6316.52,2567.57 ; v1@6429.3,2383.49 ccw(c6419.91,2374.1) 6419.91,2387.37 ccw(c6419.91,2400.65) v1@6429.3,2391.26 ; C242.2@6495.89,1514.78 ccw(c6485.97,1524.7) 6500,1524.7 ccw(c6514.03,1524.7) C242.2@6504.11,1514.78 ; v4@6495.89,1540.89 cw(c6485.97,1530.97) 6500,1530.97 cw(c6514.03,1530.97) v4@6504.11,1540.89 ; C246.2@6495.89,1664.78 ccw(c6469.42,1691.25) 6506.86,1691.25 ; C241.2@6495.89,1814.78 ccw(c6485.97,1824.7) 6500,1824.7 ccw(c6514.03,1824.7) C241.2@6504.11,1814.78 ; U48.8@6497.8,2990.43 6532.63,2990.43 6531.97,2991.1 6531.97,3016.02 ; U48.7@6497.8,3016.02 6531.97,3016.02 ; U48.6@6497.8,3041.61 6531.97,3041.61 ; v4(6500,1545) C242.2@6500,1510.67 C242.2@6502.19,1508.48 ; C241.2@6500,1810.67 6500,1833.37 6500.19,1833.37 ; C245.2@6500,1960.67 6511.86,1960.67 ; C240.2@6500,2104.86 cw(c6500,2090.83) 6509.92,2100.75 cw(c6519.84,2110.67) C240.2@6505.81,2110.67 ; C240.2@6500,2110.67 6522.19,2088.48 v1(6522.19,2000) ; v4@6500.89,2650.89 cw(c6490.97,2640.97) 6505,2640.97 cw(c6519.03,2640.97) v4@6509.11,2650.89 ; v4@6500.89,2659.11 ccw(c6490.97,2669.03) 6505,2669.03 ccw(c6519.03,2669.03) v4@6509.11,2659.11 ; C202.2@6501.1,2588.27 ccw(c6486.6,2615) 6517.01,2615 ccw(c6547.41,2615) C202.2@6532.92,2588.27 ; v5@6501.63,5953.48 6501.73,5953.37 v5(6501.73,5949.34) ; C245.2@6503.37,1955.94 cw(c6509.87,1946.83) 6517.79,1954.74 ; C224.2@6504.11,2256.56 cw(c6514.03,2246.64) 6514.03,2260.67 cw(c6514.03,2274.7) C224.2@6504.11,2264.78 ; C245.2@6504.59,1957.11 cw(c6511.86,1951.48) 6511.86,1960.67 ; C245.2@6504.59,1964.23 ccw(c6511.86,1969.86) 6511.86,1960.67 ; v4@6506.86,2653.14 v4(6505,2655) ; C246.2@6509.74,1650.82 ccw(c6500,1641.08) C246.2@6500,1654.86 ; C246.2@6509.99,1650.57 cw(c6520.09,1660.67) 6505.81,1660.67 ccw(c6519.84,1660.67) 6509.92,1650.75 ccw(c6500,1640.83) C246.2@6500,1654.86 ; C189.2@6510.18,2693.4 cw(c6508.43,2685) 6517.01,2685 ; C202.2@6517.01,2555 6517.01,2615 6505,2627.01 v4(6505,2655) ; C189.2@6517.01,2730 6517.01,2685 ; 6517.71,1647.52 ccw(c6500,1629.81) C246.2@6500,1654.86 ; v1@6518.3,2003.89 ccw(c6508.91,2013.28) 6522.19,2013.28 ccw(c6535.47,2013.28) v1@6526.08,2003.89 ; 6518.77,2260.67 cw(c6518.77,2239.02) v1@6538.42,2248.1 ; U48.8@6523.74,2991.06 ccw(c6503.88,3010.92) 6531.97,3010.92 ; U48.7@6523.74,3015.39 cw(c6503.88,2995.53) 6531.97,2995.53 ; U48.7@6523.74,3016.65 ccw(c6503.88,3036.52) 6531.97,3036.52 ; U48.6@6523.74,3040.99 cw(c6503.88,3021.12) 6531.97,3021.12 ; C189.2@6523.83,2693.4 ccw(c6525.59,2685) 6517.01,2685 ; U48.6@6524.38,3042.5 ccw(c6524.55,3062.55) 6538.73,3048.37 ; U48.8@6524.6,2989.57 cw(c6527.84,2977.38) 6536.77,2986.3 ; U48.8@6524.66,2989.59 cw(c6528.29,2979.15) 6536.1,2986.97 ; v1@6527.53,2243.07 ccw(c6500,2230.34) C224.2@6500,2260.67 6529.33,2260.67 6532.52,2257.48 v1(6532.52,2245.37) ; v1@6542.3,5454.49 cw(c6532.93,5445.12) 6546.18,5445.12 ; R130.1@6542.42,5414.25 ccw(c6533.34,5423.33) 6546.18,5423.33 ccw(c6559.02,5423.33) R130.1@6549.94,5414.25 ; R130.1@6546.18,5410 v1(6546.19,5458.37) ; 6546.18,5445.07 cw(c6559.49,5445.07) v1@6550.08,5454.49 ; v1(6554.52,4650.04) 6560.23,4655.75 U17.34@6619.41,4655.75 ; v1@6558.41,4646.15 cw(c6581.58,4622.98) 6581.58,4655.75 ; v1(6578.52,1339.37) 6565.19,1352.71 6565.19,1488.37 6531.86,1521.71 6531.86,1558.37 6548.52,1575.04 6565.19,1575.04 6581.86,1591.71 6581.86,1625.04 6565.19,1641.71 6523.52,1641.71 C246.2@6506.86,1658.37 ; SW3.3@6586.21,1085.25 ccw(c6558.04,1113.42) 6597.87,1113.42 ccw(c6637.71,1113.42) SW3.3@6609.54,1085.25 ; SW3.3@6597.87,1073.58 6597.87,1124.37 6614.87,1141.37 6615.19,1141.37 6631.86,1158.04 6631.86,1160.71 v1(6637.86,1166.71) 6673.29,1202.14 6673.29,1337.37 C221.2@6655.67,1355 ; v1@6609.69,3026.37 ccw(c6596.41,3026.37) 6605.8,3035.76 ccw(c6615.19,3045.15) v1@6615.19,3031.87 ; v1(6615.19,3026.37) 6593.19,3048.37 6538.73,3048.37 ; Q8.3@6615.43,5241.18 ccw(c6605.16,5255.04) 6622.4,5255.04 ; U13.28@6619.41,3355.55 6670.7,3355.55 6683.52,3368.37 v1(6683.52,3375.71) ; U13.41@6619.41,3765 6645,3765 v1(6670,3790) ; U13.46@6619.41,3922.48 6663.52,3922.48 6665.19,3924.15 v1(6665.19,3941.71) ; U13.52@6619.41,4111.46 6655.86,4111.46 6667.52,4123.12 v1(6667.52,4158.37) 6650.86,4175.04 6623.52,4175.04 6623.52,4174.45 U13.54@6619.41,4174.45 ; Q8.3@6622.12,5231.76 cw(c6673.62,5233.27) 6637.19,5269.7 ; Q8.3@6622.4,5230.79 6622.4,5255.04 ; 6626.58,1152.77 ccw(c6612.64,1166.71) v1@6632.36,1166.71 ; Q8.3@6629.38,5241.18 cw(c6639.65,5255.04) 6622.4,5255.04 ; Q8.3@6634.11,5232.11 cw(c6711.84,5234.39) v1@6656.85,5289.37 ; U13.41@6636.97,3769 ccw(c6636.97,3798.05) 6657.51,3777.51 ; U13.54@6636.97,4170.45 cw(c6636.97,4125.83) v1@6668.52,4157.38 ; U13.54@6636.97,4182.45 cw(c6636.97,4166.8) 6648.03,4177.87 ; v1@6637.86,1172.21 ccw(c6637.86,1185.49) 6647.25,1176.1 ccw(c6656.64,1166.71) v1@6643.36,1166.71 ; U13.54@6638.78,4170.88 cw(c6646.31,4156.02) 6658.1,4167.8 ; U13.54@6639.8,4171.62 cw(c6648.05,4163.36) 6648.05,4175.04 ; 6639.93,5272.44 ccw(c6612.33,5300.04) v1@6651.36,5300.04 ; C221.2@6655.67,1349.19 cw(c6655.67,1335.16) 6665.59,1345.08 cw(c6675.51,1355) C221.2@6661.48,1355 ; C215.2@6655.67,2375.04 v1@6702.52,2375.04 ; v1(6656.86,5300.04) v1@6656.86,5289.37 ; C215.2@6659.78,2370.89 cw(c6669.8,2360.87) 6669.8,2375.04 ; C215.2@6659.78,2379.11 ccw(c6669.6,2388.93) 6669.6,2375.04 ; v1@6661.3,3937.82 cw(c6651.91,3928.43) 6665.19,3928.43 cw(c6678.47,3928.43) v1@6669.08,3937.82 ; v1@6662.02,4158.37 ccw(c6648.75,4158.37) 6658.13,4167.76 ccw(c6667.52,4177.15) v1@6667.52,4163.87 ; v1@6663.64,4154.49 cw(c6654.25,4145.1) 6667.52,4145.1 cw(c6680.8,4145.1) v1@6671.41,4154.49 ; v1@6664.5,3790 cw(c6651.22,3790) 6660.61,3780.61 cw(c6670,3771.22) v1@6670,3784.5 ; v1@6672.93,4737.11 ccw(c6688.48,4752.67) 6688.48,4730.67 ; 6674.37,3359.22 ccw(c6663.6,3369.99) v1@6678.24,3374.19 ; v1(6677.52,4741.71) 6688.56,4730.67 C80.2@6735,4730.67 6768.52,4697.14 6768.52,4616.37 v1(6767.19,4615.04) ; 6678.79,2375.04 cw(c6678.79,2346.97) v1@6698.64,2366.82 ; v1@6681.41,4745.6 ccw(c6717.45,4781.64) 6717.45,4730.67 ; v1@6694.64,4616.15 cw(c6685.25,4606.76) 6698.52,4606.76 cw(c6711.8,4606.76) v1@6702.41,4616.15 ; v1(6698.52,4620.04) 6698.52,4595.04 6703.6,4589.96 C83.2@6735,4589.96 ; v1(6723.19,3552.71) 6723.19,3545.18 6740,3528.37 C68.2@6740,3495.51 ; v1@6728.68,3552.33 ccw(c6754.64,3550.54) 6736.24,3532.14 ; C84.2@6730.89,4403.81 cw(c6720.97,4393.89) 6735,4393.89 cw(c6749.03,4393.89) C84.2@6739.11,4403.81 ; C83.2@6730.89,4585.85 ccw(c6720.97,4575.94) 6720.97,4589.96 ccw(c6720.97,4603.99) C83.2@6730.89,4594.07 ; C80.2@6730.89,4726.56 ccw(c6720.97,4716.64) 6720.97,4730.67 ccw(c6720.97,4744.7) C80.2@6730.89,4734.78 ; C84.2@6735,4407.92 6735,4391.71 6743.33,4383.37 6748.52,4383.37 v1(6748.52,4335.04) ; C80.2@6735,4724.86 cw(c6735,4710.83) 6744.92,4720.75 cw(c6754.84,4730.67) C80.2@6740.81,4730.67 ; C79.2@6735,4830.04 6735,4822.56 v1(6768.19,4789.37) ; C68.2@6735.89,3499.62 ccw(c6725.97,3509.54) 6740,3509.54 ccw(c6754.03,3509.54) C68.2@6744.11,3499.62 ; C67.2@6740,3678.11 6764.26,3678.11 6777.52,3691.37 6777.52,3816 6789.52,3827.99 6791.24,3827.99 ; C66.2@6740,3860.16 6774.31,3860.16 6777.52,3856.94 6777.52,3841.71 6791.24,3827.99 ; C65.2@6740,4028.67 cw(c6740,4014.65) 6749.92,4024.57 cw(c6759.84,4034.48) C65.2@6745.81,4034.48 ; C65.2@6740,4034.48 6759.11,4015.37 6759.19,4015.37 v1(6766.19,4008.37) 6774.78,4016.97 U12.6@6845.59,4016.97 ; C79.2@6740.81,4830.04 ccw(c6772.88,4830.04) 6750.2,4807.36 ; C67.2@6744.11,3674 cw(c6754.03,3664.08) 6754.03,3678.11 cw(c6754.03,3692.14) C67.2@6744.11,3682.22 ; C66.2@6744.11,3856.05 cw(c6754.03,3846.13) 6754.03,3860.16 cw(c6754.03,3874.19) C66.2@6744.11,3864.27 ; v1@6744.64,4338.93 ccw(c6735.25,4348.32) 6748.52,4348.32 ccw(c6761.8,4348.32) v1@6752.41,4338.93 ; 6756.66,4017.82 ccw(c6766.19,4027.35) v1@6766.19,4013.87 ; 6756.86,4017.63 cw(c6747.61,4008.37) v1@6760.69,4008.37 ; v1@6762.69,4789.37 ccw(c6749.41,4789.37) 6758.8,4798.76 ccw(c6768.19,4808.15) v1@6768.19,4794.87 ; v1@6763.3,4618.93 ccw(c6750.69,4631.54) 6768.52,4631.54 ; v1@6770.08,4004.49 cw(c6800.21,3974.35) 6800.21,4016.97 ; v1@6788.3,2965.93 ccw(c6778.91,2975.32) 6792.19,2975.32 ccw(c6805.47,2975.32) v1@6796.08,2965.93 ; SW8.1@6790,110.71 6890,110.71 6990,110.71 7090,110.71 7190,110.71 SW8.6@7290,110.71 ; v1(6792.19,2962.04) 6792.19,2980.71 6791.46,2981.44 6791.46,3016.46 U34.7@6820,3016.46 ; SW8.1@6793,98.5 cw(c6822.49,69.01) 6822.49,110.71 ; SW8.1@6801.49,90.01 cw(c6851.46,40.04) 6851.46,110.71 ; C237.2@6801.56,1350.89 cw(c6791.64,1340.97) 6805.67,1340.97 cw(c6819.7,1340.97) C237.2@6809.78,1350.89 ; v1@6801.78,1323.41 ccw(c6792.39,1332.8) 6805.67,1332.8 ccw(c6818.95,1332.8) v1@6809.56,1323.41 ; v1@6805.67,1319.33 v1(6805.67,1319.52) C237.2@6805.67,1355 ; C231.2@6805.67,2375 v1(6845,2375) C196.2@6914.33,2375 ; C231.2@6809.78,2370.89 cw(c6819.7,2360.97) 6819.7,2375 ; C231.2@6809.78,2379.11 ccw(c6819.7,2389.03) 6819.7,2375 ; 6828.54,110.71 cw(c6828.54,40.04) SW8.2@6878.51,90.01 ; v1@6841.11,2371.11 ccw(c6831.72,2361.72) 6831.72,2375 ccw(c6831.72,2388.28) v1@6841.11,2378.89 ; U16.12@6845.59,4624.25 6878.52,4624.25 6880.86,4626.58 6880.86,4633.37 6890.19,4642.71 v1(6890.19,4658.37) ; v1@6848.89,2371.11 cw(c6858.28,2361.72) 6858.28,2375 cw(c6858.28,2388.28) v1@6848.89,2378.89 ; 6857.51,110.71 cw(c6857.51,69.01) SW8.2@6887,98.5 ; 6873.34,3827.99 ccw(c6873.34,3869.89) v1@6902.97,3840.26 ; SW8.2@6893,98.5 cw(c6922.49,69.01) 6922.49,110.71 ; v1(6900,1310) 6914.33,1324.33 C198.2@6914.33,1355 ; SW8.2@6901.49,90.01 cw(c6951.46,40.04) 6951.46,110.71 ; v1(6906.86,3836.37) 6898.47,3827.99 U12.12@6845.59,3827.99 6791.24,3827.99 ; C198.2@6910.22,1350.89 cw(c6900.3,1340.97) 6914.33,1340.97 cw(c6928.36,1340.97) C198.2@6918.44,1350.89 ; C196.2@6910.22,2370.89 ccw(c6900.3,2360.97) 6900.3,2375 ccw(c6900.3,2389.03) C196.2@6910.22,2379.11 ; 6928.54,110.71 cw(c6928.54,40.04) SW8.3@6978.51,90.01 ; C123.1@6945.67,2965 6988.86,2965 7003.52,2950.33 7003.52,2950.04 ; C123.1@6949.78,2960.89 cw(c6959.7,2950.97) 6959.7,2965 ; C123.1@6949.78,2969.11 ccw(c6959.7,2979.03) 6959.7,2965 ; 6957.51,110.71 cw(c6957.51,69.01) SW8.3@6987,98.5 ; SW8.3@6993,98.5 cw(c7022.49,69.01) 7022.49,110.71 ; 6995.47,2958.39 cw(c6976.08,2939) v1@7003.5,2939 ; SW8.3@7001.49,90.01 cw(c7051.46,40.04) 7051.46,110.71 ; 7028.54,110.71 cw(c7028.54,40.04) SW8.4@7078.51,90.01 ; 7049.37,2258.7 7049.37,2288.22 7115.57,2354.43 7119.52,2358.37 7125,2358.37 7130.67,2358.37 C197.2@7130.67,2375 ; 7057.51,110.71 cw(c7057.51,69.01) SW8.4@7087,98.5 ; SW4.3@7075.37,1073.19 7116.04,1073.19 ; SW8.4@7078.51,112.98 ccw(c7050.78,140.71) 7090,140.71 ccw(c7129.22,140.71) SW8.4@7101.49,112.98 ; 7083.43,2322.28 cw(c7125,2280.71) v1@7125,2339.5 ; SW8.4@7084.65,116.83 ccw(c7082.01,124.37) 7090,124.37 ; v1@7086.11,335.96 cw(c7076.72,326.57) 7090,326.57 cw(c7103.28,326.57) v1@7093.89,335.96 ; v1@7091.19,1225.87 cw(c7091.19,1212.6) 7100.58,1221.99 cw(c7109.97,1231.37) v1@7096.69,1231.37 ; v1(7091.19,1231.37) 7124.52,1198.04 7124.52,1081.67 7116.04,1073.19 ; SW8.4@7093,98.5 cw(c7122.49,69.01) 7122.49,110.71 ; v1@7093.52,343.37 7090,339.85 7090,124.37 ; SW4.3@7094.18,1062.78 cw(c7116.04,1045.02) 7116.04,1073.19 ; SW4.3@7094.18,1083.59 ccw(c7116.04,1101.36) 7116.04,1073.19 ; SW8.4@7095.35,116.83 cw(c7097.99,124.37) 7090,124.37 ; SW8.4@7101.49,90.01 cw(c7151.46,40.04) 7151.46,110.71 ; Q11.3@7102.22,2645.02 cw(c7113.21,2631.9) 7125.31,2644 ; Q11.3@7102.3,2645.07 cw(c7111.77,2621.11) 7129.99,2639.32 ; Q11.3@7102.4,2645.79 7123.52,2645.79 ; 7103.92,2342.77 cw(c7125,2321.68) v1@7125,2351.5 ; C199.2@7105.67,1355 7154.23,1355 v1(7154.52,1354.71) ; C199.2@7109.78,1350.89 cw(c7119.7,1340.97) 7119.7,1355 ; C199.2@7109.78,1359.11 ccw(c7119.7,1369.03) 7119.7,1355 ; Q11.3@7109.92,2635.82 cw(c7121.66,2621.81) 7134.58,2634.73 ; Q11.3@7112.34,2639.58 cw(c7123.52,2632.61) 7123.52,2645.79 ; Q11.3@7112.34,2651.99 ccw(c7123.52,2658.97) 7123.52,2645.79 ; 7118.32,2357.17 ccw(c7102.37,2373.11) C197.2@7124.87,2374.61 ; v1@7121.11,2348.89 ccw(c7098.04,2371.96) C197.2@7130.67,2371.96 ; 7122.26,2361.12 ccw(c7113.88,2369.5) C197.2@7125.15,2373.19 ; C197.2@7126.56,2370.89 cw(c7116.64,2360.97) 7130.67,2360.97 cw(c7144.7,2360.97) C197.2@7134.78,2370.89 ; 7128.54,110.71 cw(c7128.54,40.04) SW8.5@7178.51,90.01 ; U35.7@7130,3016.46 7163.52,3016.46 7163.52,2976.71 v1(7198.52,2941.71) 7206.86,2950.04 7206.86,2950.33 7216.52,2960 ; 7140.54,1355 cw(c7140.54,1340.72) v1@7150.64,1350.82 ; 7141.95,1355 ccw(c7141.95,1367.28) v1@7150.64,1358.6 ; U35.7@7156.48,3016.46 cw(c7139.48,2999.45) 7163.52,2999.45 ; 7157.51,110.71 cw(c7157.51,69.01) SW8.5@7187,98.5 ; SW8.5@7193,98.5 cw(c7222.49,69.01) 7222.49,110.71 ; v1@7193.02,2941.71 ccw(c7179.75,2941.71) 7189.14,2951.1 ccw(c7198.52,2960.49) 7198.52,2947.21 ccw(c7198.52,2959.78) 7207.41,2950.89 ; SW8.5@7201.49,90.01 cw(c7251.46,40.04) 7251.46,110.71 ; v1@7204.02,2941.71 cw(c7218.01,2941.71) 7208.12,2951.6 ; 7210.12,2953.6 cw(c7219.07,2944.65) C125.1@7226.1,2955.17 ; C125.1@7224.96,2956.17 ccw(c7216.52,2948.79) 7216.52,2960 ; C125.1@7224.96,2963.83 cw(c7216.52,2971.2) 7216.52,2960 ; 7228.54,110.71 cw(c7228.54,40.04) SW8.6@7278.51,90.01 ; C125.1@7229.33,2960 7216.52,2960 ; 7250.26,4096.44 cw(c7276.85,4069.85) U12.52@7276.85,4107.46 ; v1@7250.97,1327.26 ccw(c7239.62,1338.61) 7255.67,1338.61 ; C223.2@7251.56,1350.89 cw(c7241.64,1340.97) 7255.67,1340.97 cw(c7269.7,1340.97) C223.2@7259.78,1350.89 ; v1(7254.86,1323.37) 7255.67,1324.19 C223.2@7255.67,1355 ; C217.2@7255.67,2375 7275.19,2375 7290.19,2390 ; 7257.51,110.71 cw(c7257.51,69.01) SW8.6@7287,98.5 ; 7259.4,4105.58 cw(c7268.77,4096.22) U12.52@7274.98,4107.92 ; C217.2@7259.78,2370.89 cw(c7269.7,2360.97) 7269.7,2375 cw(c7269.7,2389.03) C217.2@7259.78,2379.11 ; 7265.76,4175.04 cw(c7265.76,4163.36) U12.54@7274.02,4171.62 ; SW8.6@7278.51,112.98 ccw(c7250.78,140.71) 7290,140.71 ccw(c7329.22,140.71) SW8.6@7301.49,112.98 ; v1@7286.11,161.11 cw(c7276.72,151.72) 7290,151.72 cw(c7303.28,151.72) v1@7293.89,161.11 ; SW8.6@7290,75.71 SW8.6@7290,110.71 ; v1(7290,165) SW8.6@7290,110.71 ; 7290.19,2389.04 7290.19,2390 ; SW8.6@7293,98.5 cw(c7322.49,69.01) 7322.49,110.71 ; U12.28@7294.41,3355.55 7345.7,3355.55 7373.52,3383.37 v1(7390.19,3383.37) 7440.19,3433.37 7440.19,3489.04 7433.72,3495.51 C70.2@7385,3495.51 ; U12.41@7294.41,3765 7311.96,3765 v1@7401.9,3765 ; U12.46@7294.41,3922.48 7367.22,3922.48 7385,3904.7 C64.2@7385,3860.16 ; U12.52@7294.41,4111.46 7265.19,4111.46 7265.19,4111.37 7253.86,4100.04 7232.86,4100.04 7224.52,4108.37 7224.52,4139.04 7260.52,4175.04 7294.41,4175.04 7298.52,4175.04 U12.54@7298.52,4174.45 ; U12.54@7294.41,4174.45 U12.54@7298.52,4174.45 ; U16.34@7294.41,4655.75 7334.15,4655.75 v1(7346.52,4643.37) ; SW8.6@7301.49,90.01 cw(c7351.46,40.04) 7351.46,110.71 ; U16.34@7303.37,4655.75 cw(c7303.37,4600.23) v1@7342.64,4639.49 ; 7328.54,110.71 cw(c7328.54,40.04) SW8.7@7378.51,90.01 ; 7332.35,4655.75 cw(c7332.35,4629.2) v1@7351.12,4647.97 ; 7352.35,3362.2 cw(c7390.19,3324.36) v1@7390.19,3377.87 ; 7357.51,110.71 cw(c7357.51,69.01) SW8.7@7387,98.5 ; 7365.19,3375.04 cw(c7378.78,3361.46) v1@7387.65,3378.5 ; 7372.84,3382.69 cw(c7390.19,3365.33) v1@7390.19,3389.87 ; 7376.76,3386.61 cw(c7386.7,3376.67) v1@7393.19,3389.14 ; C63.2@7380.89,3723.56 ccw(c7370.97,3733.48) 7385,3733.48 ccw(c7399.03,3733.48) C63.2@7389.11,3723.56 ; C64.2@7380.89,3864.27 ccw(c7370.97,3874.19) 7385,3874.19 ccw(c7399.03,3874.19) C64.2@7389.11,3864.27 ; C69.2@7380.89,4079.93 ccw(c7370.97,4089.85) 7385,4089.85 ccw(c7399.03,4089.85) C69.2@7389.11,4079.93 ; C81.2@7380.89,4403.81 cw(c7370.97,4393.89) 7385,4393.89 cw(c7399.03,4393.89) C81.2@7389.11,4403.81 ; C85.2@7380.89,4734.78 ccw(c7370.97,4744.7) 7385,4744.7 ccw(c7399.03,4744.7) C85.2@7389.11,4734.78 ; C86.2@7381.33,4594.47 ccw(c7375.06,4602.18) 7385,4602.18 ; C63.2@7385,3719.45 7385,3745.04 ; C69.2@7385,4075.82 7385,4121.52 7413.52,4150.04 v1(7440.19,4150.04) v1(7440.19,4150.04) 7415.86,4174.45 U12.54@7298.52,4174.45 ; C81.2@7385,4407.92 7385,4385.04 7386.67,4383.37 7398.52,4383.37 7418.19,4363.71 v1(7418.19,4359.04) ; C86.2@7385,4589.96 7385,4602.18 ; C85.2@7385,4724.86 cw(c7385,4710.83) 7394.92,4720.75 cw(c7404.84,4730.67) C85.2@7390.81,4730.67 ; C85.2@7385,4733.14 cw(c7438.76,4733.14) v1@7400.75,4771.15 ; 7385,4762.11 cw(c7409.79,4762.11) v1@7392.26,4779.64 ; C82.2@7385,4871.38 7419.86,4871.38 7423.52,4871.37 ; 7385.19,3745.04 v1(7403.52,3763.37) ; v1@7386.3,3379.49 ccw(c7376.91,3370.1) 7376.91,3383.37 ccw(c7376.91,3396.65) v1@7386.3,3387.26 ; 7386.32,3765 cw(c7386.32,3746.17) v1@7399.64,3759.49 ; C86.2@7388.67,4594.47 cw(c7394.95,4602.18) 7385,4602.18 ; C70.2@7389.11,3491.41 cw(c7399.03,3481.49) 7399.03,3495.51 cw(c7399.03,3509.54) C70.2@7389.11,3499.62 ; C82.2@7389.11,4867.27 cw(c7399.03,4857.35) 7399.03,4871.38 cw(c7399.03,4885.41) C82.2@7389.11,4875.49 ; C184.2@7389.99,2695.33 cw(c7381.69,2675.71) 7402.99,2675.71 ; v1@7390.19,3388.87 ccw(c7390.19,3402.15) 7399.58,3392.76 ccw(c7408.97,3383.37) v1@7395.69,3383.37 ; C201.2@7390.51,2589.89 ccw(c7383.06,2608.37) 7402.99,2608.37 ; C64.2@7390.79,3865.95 7406.7,3850.04 v1(7431.86,3850.04) ; C86.2@7390.81,4589.96 cw(c7434.34,4589.96) 7403.56,4620.75 ; SW8.7@7393,98.5 cw(c7422.49,69.01) 7422.49,110.71 ; C201.2@7395.98,2563.9 cw(c7414.91,2529.25) 7442.83,2557.17 ; v1(7396.86,4775.04) 7388.52,4775.04 7385,4771.52 C85.2@7385,4730.67 7406.86,4708.81 7406.86,4703.04 v1(7433.86,4676.04) 7433.86,4651.04 7385,4602.18 ; v1@7398.02,3763.37 cw(c7384.75,3763.37) 7394.14,3753.99 cw(c7403.52,3744.6) v1@7403.52,3757.87 ; SW8.7@7401.49,90.01 cw(c7451.46,40.04) 7451.46,110.71 ; C233.2@7401.56,2379.11 ccw(c7391.64,2389.03) 7405.67,2389.03 ccw(c7419.7,2389.03) C233.2@7409.78,2379.11 ; C201.2@7401.73,2553.37 cw(c7422.92,2514.59) 7454.16,2545.84 ; v1@7402.36,2407.37 ccw(c7389.08,2407.37) 7398.47,2416.76 ccw(c7407.86,2426.15) v1@7407.86,2412.87 ; C184.2@7402.99,2730 7402.99,2675.71 ; 7405.5,4376.4 cw(c7388.15,4359.04) v1@7412.69,4359.04 ; C239.2@7405.67,1349.19 cw(c7405.67,1335.16) 7415.59,1345.08 cw(c7425.51,1355) C239.2@7411.48,1355 ; C239.2@7405.67,1355 7431.86,1328.81 v1(7431.86,1308.37) ; C233.2@7405.67,2375 7405.67,2399.71 v1@7413.34,2407.37 ; 7405.67,2388.81 cw(c7426.42,2388.81) v1@7411.75,2403.49 ; C201.2@7407.48,2542.84 cw(c7430.92,2499.93) 7465.5,2534.5 ; v1@7413.3,4923.82 cw(c7388.62,4899.14) 7423.52,4899.14 ; v1@7413.67,2407.71 v1@7413.34,2407.37 ; C201.2@7415.47,2589.89 cw(c7422.93,2608.37) 7402.99,2608.37 ; C184.2@7416,2695.33 ccw(c7424.3,2675.71) 7402.99,2675.71 ; v1(7417.19,4927.71) 7423.52,4921.37 7423.52,4871.37 ; v1@7427.97,1312.26 ccw(c7418.58,1321.65) 7431.86,1321.65 ccw(c7445.14,1321.65) v1@7435.75,1312.26 ; v1@7427.97,3846.15 ccw(c7418.58,3836.76) 7418.58,3850.04 ccw(c7418.58,3863.32) v1@7427.97,3853.93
